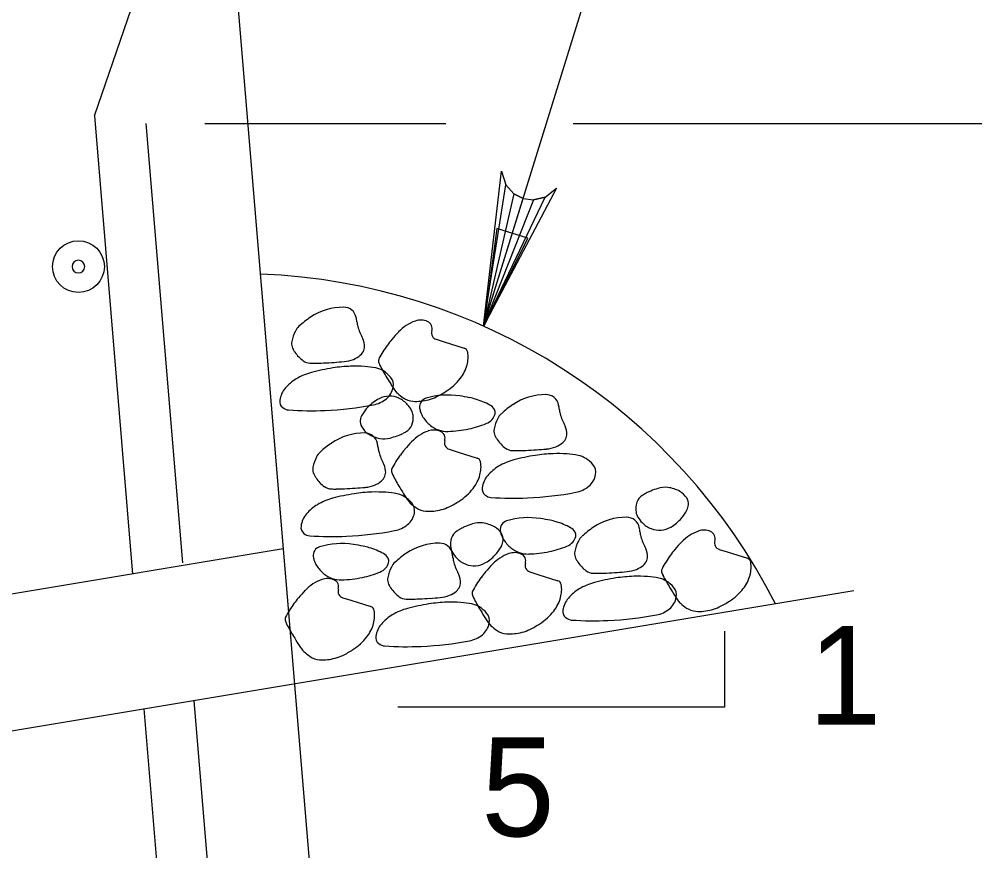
# Model space of a CAD drawing. Extents: x 634540 to 640306, y 296059 to 300275.
# Drawn here: x 639979.48 to 640008.5, y 298249.68 to 298274.94 of the extents above; entities that cross this region are included whole.
import ezdxf

# ---------------------------------------------------------------- set-up
doc = ezdxf.new("R2010")
doc.units = 0
for name, color, linetype in [('3', 7, 'Continuous'), ('4', 7, 'Continuous'), ('6', 7, 'Continuous'), ('8', 7, 'Continuous'), ('9', 7, 'Continuous')]:
    doc.layers.add(name, color=color, linetype=linetype)

# ---------------------------------------------------------------- blocks, each defined once
blk = doc.blocks.new('B')
at = {"layer": '3'}
blk.add_circle((0, 0), 0.1599, dxfattribs=at)
for start, end in [(0, 180), (180, 0)]:
    blk.add_arc((0, 0), 0.0391, start, end, dxfattribs=at)

msp = doc.modelspace()

# ---------------------------------------------------------------- linework, layer by layer
at = {"layer": '4'}
for p, q in [((639993.578, 298265.615), (639999.839, 298285.82)), ((639985.118, 298271.77), (639992.434, 298271.77)), ((639996.304, 298271.77), (640045.119, 298271.77))]:
    msp.add_line(p, q, dxfattribs=at)
for points in [[(639993.578, 298265.615), (639994.122, 298270.326), (639994.255, 298269.909), (639994.497, 298269.64), (639994.78, 298269.496), (639995.095, 298269.455), (639995.449, 298269.538), (639995.793, 298269.809), (639993.578, 298265.615), (639995.449, 298269.538), (639995.095, 298269.455), (639993.578, 298265.615), (639994.78, 298269.496), (639994.497, 298269.64), (639993.578, 298265.615), (639994.255, 298269.909)], [(640000.895, 298256.35), (640000.895, 298254.044), (639990.972, 298254.044)]]:
    msp.add_lwpolyline(points, dxfattribs=at)
msp.add_lwpolyline([(639994.922, 298268.29), (639993.98, 298268.578), (639993.591, 298265.609)], close=True, dxfattribs=at)
at = {"layer": '6'}
for p, q in [((639981.765, 298272.003), (639983.007, 298275.626)), ((639981.765, 298272.003), (639982.925, 298258.086)), ((639983.328, 298271.769), (639984.44, 298258.427)), ((639984.788, 298254.242), (639989.938, 298192.437)), ((639983.267, 298253.987), (639986.817, 298211.379))]:
    msp.add_line(p, q, dxfattribs=at)
at = {"layer": '8'}
for points in [[(639992.14, 298265.217), (639992.384, 298265.14), (639992.995, 298264.946)], [(639992.532, 298261.877), (639992.776, 298261.8), (639993.388, 298261.609)], [(640000.733, 298258.836), (640000.978, 298258.758), (640001.589, 298258.567)], [(639994.98, 298258.154), (639995.226, 298258.075), (639995.836, 298257.883)], [(639989.303, 298257.367), (639989.549, 298257.29), (639990.159, 298257.096)]]:
    msp.add_lwpolyline(points, dxfattribs=at)
for centre, radius, start, end in [((639989.318, 298264.416), 1.776, 89.5772, 124.1443), ((639989.328, 298265.798), 0.395, 11.4529, 89.5772), ((639989.973, 298263.45), 2.944, 124.1443, 132.7374), ((639988.393, 298265.608), 1.349, 6.1004, 11.4529), ((639991.676, 298265.297), 0.503, 65.9597, 109.6635), ((639988.319, 298265.24), 0.507, 132.7374, 153.538), ((639990.636, 298265.848), 0.907, 186.1004, 192.6291), ((639991.052, 298265.941), 1.333, 192.6291, 208.6753), ((639991.943, 298264.548), 1.298, 109.6635, 136.4562), ((639991.787, 298265.545), 0.231, 342.3569, 65.9597), ((639989.015, 298264.894), 1.284, 153.538, 168.4897), ((639989.272, 298264.968), 0.696, 6.391, 28.6753), ((639992.931, 298263.399), 2.801, 139.6491, 144.1424), ((639995.023, 298261.622), 5.547, 136.4562, 139.6491), ((639992.202, 298265.413), 0.205, 162.3569, 252.4715), ((639988.061, 298265.088), 0.311, 168.4897, 199.1639), ((639988.291, 298265.168), 0.554, 199.1639, 207.4728), ((639989.621, 298265.007), 0.344, 338.0834, 6.391), ((639993.462, 298263.015), 3.458, 144.1424, 152.1777), ((639992.951, 298264.806), 0.148, 9.0416, 72.4715), ((639988.584, 298265.32), 0.884, 207.4728, 214.0468), ((639988.726, 298265.416), 1.056, 214.0468, 234.0353), ((639989.362, 298265.283), 0.726, 291.5731, 310.9894), ((639989.592, 298265.018), 0.375, 310.9894, 338.0834), ((639990.525, 298264.565), 0.136, 152.1777, 193.5774), ((639992.171, 298264.682), 0.939, 344.9373, 9.0416), ((639988.321, 298264.859), 0.367, 234.0353, 268.2715), ((639988.412, 298267.862), 3.372, 268.2715, 270.9097), ((639990.026, 298257.942), 6.485, 99.0416, 104.9239), ((639988.327, 298273.236), 8.746, 270.9097, 272.5478), ((639988.079, 298278.805), 14.321, 272.5478, 273.846), ((639989.677, 298260.133), 4.267, 91.7881, 99.0416), ((639988.171, 298277.434), 12.947, 273.846, 275.2114), ((639989.254, 298265.556), 1.019, 275.2114, 291.5731), ((639989.675, 298260.197), 4.203, 86.0442, 91.7881), ((639989.771, 298261.584), 2.813, 79.021, 86.0442), ((639990.174, 298263.66), 0.698, 58.4341, 79.021), ((639990.862, 298264.646), 0.482, 193.5774, 207.4728), ((639996.193, 298267.418), 6.491, 207.4728, 211.2525), ((639991.97, 298264.736), 1.147, 321.7572, 344.9373), ((639988.821, 298262.461), 1.809, 104.9239, 120.8473), ((639990.057, 298263.47), 0.921, 40.5338, 58.4341), ((640005.472, 298273.05), 17.346, 211.2525, 212.2356), ((639990.478, 298263.831), 0.366, 349.0625, 40.5338), ((639988.593, 298262.843), 1.364, 120.8473, 139.2037), ((639990.245, 298263.876), 0.604, 309.5539, 349.0625), ((639993.996, 298265.813), 3.778, 212.2356, 214.3424), ((639991.491, 298265.113), 1.756, 303.0692, 321.7572), ((639988.099, 298263.269), 0.712, 139.2037, 172.3458), ((639990.727, 298262.8), 0.69, 91.376, 117.4803), ((639990.727, 298262.809), 0.681, 65.3457, 91.376), ((639991.351, 298264.006), 0.575, 214.3424, 227.6953), ((639992.158, 298264.892), 1.774, 227.6953, 235.2847), ((639992.504, 298261.197), 2.327, 81.3134, 106.8084), ((639991.555, 298264.685), 1.351, 285.2565, 295.7443), ((639990.941, 298265.958), 2.765, 295.7443, 303.0692), ((639991.925, 298257.406), 6.162, 78.4814, 81.3134), ((639995.462, 298261.761), 1.776, 89.5772, 124.1443), ((639995.472, 298263.142), 0.395, 11.4529, 89.5772), ((639987.639, 298263.331), 0.247, 172.3458, 230.2635), ((639988.352, 298273.126), 10.078, 272.3841, 280.7777), ((639991.006, 298262.264), 1.295, 117.4803, 136.4654), ((639990.073, 298264.084), 0.874, 280.7777, 309.5539), ((639990.685, 298262.718), 0.78, 41.057, 65.3457), ((639991.472, 298263.903), 0.569, 235.2847, 266.0442), ((639990.588, 298262.633), 0.91, 27.4728, 41.057), ((639991.532, 298264.769), 1.438, 266.0442, 285.2565), ((639991.911, 298263.161), 0.275, 106.8084, 186.6218), ((639992.7, 298261.208), 2.282, 73.8272, 78.4814), ((639992.741, 298261.349), 2.134, 61.1605, 73.8272), ((639993.598, 298262.907), 0.357, 29.8544, 61.1605), ((639996.117, 298260.795), 2.944, 124.1443, 132.7374), ((639994.537, 298262.953), 1.349, 6.1004, 11.4529), ((639987.681, 298263.382), 0.312, 230.2635, 266.2346), ((639988.34, 298273.403), 10.356, 266.2346, 272.3841), ((639990.249, 298262.713), 0.414, 149.2422, 171.9761), ((639991.01, 298262.26), 1.3, 136.4654, 149.2422), ((639990.999, 298262.847), 0.447, 8.0357, 27.4728), ((639990.871, 298262.829), 0.576, 337.0418, 8.0357), ((639992.219, 298263.197), 0.585, 186.6218, 200.3491), ((639992.337, 298263.241), 0.711, 200.3491, 212.797), ((639993.561, 298263.036), 0.376, 317.8475, 347.2445), ((639993.749, 298262.993), 0.183, 347.2445, 29.8544), ((639994.463, 298262.584), 0.507, 132.7374, 153.538), ((639996.78, 298263.193), 0.907, 186.1004, 192.6291), ((639997.196, 298263.286), 1.333, 192.6291, 208.6753), ((639990.175, 298262.723), 0.34, 171.9761, 209.5935), ((639991.029, 298262.762), 0.404, 299.831, 337.0418), ((639992.662, 298263.45), 1.097, 212.797, 230.2213), ((639992.476, 298263.227), 0.808, 230.2213, 250.5601), ((639992.49, 298265.548), 3.119, 281.8686, 292.039), ((639993.476, 298263.113), 0.491, 292.039, 317.8475), ((639995.159, 298262.238), 1.284, 153.538, 168.4897), ((639995.416, 298262.312), 0.696, 6.391, 28.6753), ((639989.961, 298260.595), 1.776, 89.5772, 124.1443), ((639990.401, 298262.852), 0.6, 209.5935, 237.6667), ((639989.971, 298261.977), 0.395, 11.4529, 89.5772), ((639990.628, 298263.21), 1.024, 237.6667, 259.0544), ((639990.559, 298263.482), 1.262, 288.5059, 293.8705), ((639990.61, 298263.366), 1.135, 293.8705, 297.4803), ((639989.899, 298264.733), 2.676, 297.4803, 299.831), ((639992.336, 298261.209), 1.298, 109.6635, 136.4562), ((639992.068, 298261.958), 0.503, 65.9597, 109.6635), ((639992.474, 298263.221), 0.802, 250.5601, 271.915), ((639992.179, 298262.207), 0.231, 342.3569, 65.9597), ((639992.379, 298266.075), 3.657, 271.915, 281.8686), ((639994.205, 298262.432), 0.311, 168.4897, 199.1639), ((639994.435, 298262.512), 0.554, 199.1639, 207.4728), ((639995.765, 298262.351), 0.344, 338.0834, 6.391), ((639990.616, 298259.629), 2.944, 124.1443, 132.7374), ((639989.036, 298261.787), 1.349, 6.1004, 11.4529), ((639990.559, 298262.854), 0.661, 259.0544, 285.7584), ((639989.433, 298266.846), 4.81, 285.7584, 288.5059), ((639995.415, 298258.283), 5.547, 136.4562, 139.6491), ((639992.595, 298262.074), 0.205, 162.3569, 252.4715), ((639994.728, 298262.665), 0.884, 207.4728, 214.0468), ((639994.87, 298262.761), 1.056, 214.0468, 234.0353), ((639995.507, 298262.627), 0.726, 291.5731, 310.9894), ((639995.737, 298262.363), 0.375, 310.9894, 338.0834), ((639988.962, 298261.419), 0.507, 132.7374, 153.538), ((639991.279, 298262.027), 0.907, 186.1004, 192.6291), ((639991.695, 298262.12), 1.333, 192.6291, 208.6753), ((639993.323, 298260.06), 2.801, 139.6491, 144.1424), ((639994.466, 298262.203), 0.367, 234.0353, 268.2715), ((639994.556, 298265.207), 3.372, 268.2715, 270.9097), ((639994.471, 298270.58), 8.746, 270.9097, 272.5478), ((639994.223, 298276.149), 14.321, 272.5478, 273.846), ((639995.821, 298257.477), 4.267, 91.7881, 99.0416), ((639994.315, 298274.778), 12.947, 273.846, 275.2114), ((639995.399, 298262.9), 1.019, 275.2114, 291.5731), ((639995.819, 298257.541), 4.203, 86.0442, 91.7881), ((639995.915, 298258.929), 2.813, 79.021, 86.0442), ((639989.658, 298261.073), 1.284, 153.538, 168.4897), ((639989.915, 298261.147), 0.696, 6.391, 28.6753), ((639993.855, 298259.676), 3.458, 144.1424, 152.1777), ((639993.344, 298261.467), 0.148, 9.0416, 72.4715), ((639992.563, 298261.343), 0.939, 344.9373, 9.0416), ((639994.965, 298259.806), 1.809, 104.9239, 120.8473), ((639996.17, 298255.287), 6.485, 99.0416, 104.9239), ((639996.318, 298261.005), 0.698, 58.4341, 79.021), ((639996.201, 298260.815), 0.921, 40.5338, 58.4341), ((639988.704, 298261.267), 0.311, 168.4897, 199.1639), ((639988.934, 298261.347), 0.554, 199.1639, 207.4728), ((639990.264, 298261.186), 0.344, 338.0834, 6.391), ((639990.917, 298261.226), 0.136, 152.1777, 193.5774), ((639991.254, 298261.308), 0.482, 193.5774, 207.4728), ((639994.737, 298260.187), 1.364, 120.8473, 139.2037), ((639996.623, 298261.175), 0.366, 349.0625, 40.5338), ((639989.227, 298261.499), 0.884, 207.4728, 214.0468), ((639989.369, 298261.595), 1.056, 214.0468, 234.0353), ((639990.006, 298261.462), 0.726, 291.5731, 310.9894), ((639990.235, 298261.197), 0.375, 310.9894, 338.0834), ((639996.585, 298264.08), 6.491, 207.4728, 211.2525), ((639992.362, 298261.397), 1.147, 321.7572, 344.9373), ((639994.244, 298260.614), 0.712, 139.2037, 172.3458), ((639996.389, 298261.22), 0.604, 309.5539, 349.0625), ((639988.965, 298261.038), 0.367, 234.0353, 268.2715), ((639989.055, 298264.041), 3.372, 268.2715, 270.9097), ((639988.97, 298269.415), 8.746, 270.9097, 272.5478), ((639988.722, 298274.984), 14.321, 272.5478, 273.846), ((639990.32, 298256.312), 4.267, 91.7881, 99.0416), ((639988.814, 298273.613), 12.947, 273.846, 275.2114), ((639989.898, 298261.735), 1.019, 275.2114, 291.5731), ((639990.318, 298256.376), 4.203, 86.0442, 91.7881), ((639990.414, 298257.763), 2.813, 79.021, 86.0442), ((640005.865, 298269.711), 17.346, 211.2525, 212.2356), ((639991.884, 298261.774), 1.756, 303.0692, 321.7572), ((639993.783, 298260.675), 0.247, 172.3458, 230.2635), ((639994.496, 298270.47), 10.078, 272.3841, 280.7777), ((639996.217, 298261.428), 0.874, 280.7777, 309.5539), ((639999.12, 298259.435), 1.262, 111.6288, 116.9933), ((640000.428, 298256.137), 4.81, 108.8812, 111.6288), ((639999.085, 298260.062), 0.661, 82.1773, 108.8812), ((639999.036, 298259.703), 1.024, 60.7895, 82.1773), ((639999.243, 298260.073), 0.6, 32.7163, 60.7895), ((639989.464, 298258.64), 1.809, 104.9239, 120.8473), ((639990.669, 298254.121), 6.485, 99.0416, 104.9239), ((639990.817, 298259.839), 0.698, 58.4341, 79.021), ((639990.7, 298259.649), 0.921, 40.5338, 58.4341), ((639994.388, 298262.474), 3.778, 212.2356, 214.3424), ((639991.743, 298260.667), 0.575, 214.3424, 227.6953), ((639991.333, 298262.62), 2.765, 295.7443, 303.0692), ((639993.825, 298260.726), 0.312, 230.2635, 266.2346), ((639994.484, 298270.747), 10.356, 266.2346, 272.3841), ((639998.611, 298260.129), 0.404, 122.9538, 160.1647), ((639999.847, 298258.222), 2.676, 120.6031, 122.9538), ((639999.063, 298259.548), 1.135, 116.9933, 120.6031), ((639999.462, 298260.214), 0.34, 355.0989, 32.7163), ((639989.236, 298259.022), 1.364, 120.8473, 139.2037), ((639992.55, 298261.554), 1.774, 227.6953, 235.2847), ((639991.122, 298260.01), 0.366, 349.0625, 40.5338), ((639991.864, 298260.564), 0.569, 235.2847, 266.0442), ((639991.924, 298261.431), 1.438, 266.0442, 285.2565), ((639991.948, 298261.346), 1.351, 285.2565, 295.7443), ((639998.773, 298260.07), 0.576, 160.1647, 191.1585), ((639998.603, 298260.631), 1.3, 319.5882, 332.365), ((639999.388, 298260.22), 0.414, 332.365, 355.0989), ((639988.743, 298259.448), 0.712, 139.2037, 172.3458), ((639990.888, 298260.055), 0.604, 309.5539, 349.0625), ((639994.36, 298259.436), 0.275, 106.8084, 186.6218), ((639994.953, 298257.472), 2.327, 81.3134, 106.8084), ((639994.374, 298253.681), 6.162, 78.4814, 81.3134), ((639995.149, 298257.482), 2.282, 73.8272, 78.4814), ((639997.911, 298258.036), 1.776, 89.5772, 124.1443), ((639997.921, 298259.417), 0.395, 11.4529, 89.5772), ((639998.646, 298260.045), 0.447, 191.1585, 210.5956), ((639999.045, 298260.281), 0.91, 210.5956, 224.1798), ((639998.607, 298260.627), 1.295, 300.6031, 319.5882), ((639988.282, 298259.51), 0.247, 172.3458, 230.2635), ((639988.995, 298269.305), 10.078, 272.3841, 280.7777), ((639990.716, 298260.263), 0.874, 280.7777, 309.5539), ((639994.222, 298257.142), 2.676, 120.6031, 122.9538), ((639993.437, 298258.468), 1.135, 116.9933, 120.6031), ((639993.495, 298258.355), 1.262, 111.6288, 116.9933), ((639994.802, 298255.057), 4.81, 108.8812, 111.6288), ((639993.46, 298258.982), 0.661, 82.1773, 108.8812), ((639993.411, 298258.623), 1.024, 60.7895, 82.1773), ((639993.618, 298258.993), 0.6, 32.7163, 60.7895), ((639994.668, 298259.472), 0.585, 186.6218, 200.3491), ((639995.19, 298257.624), 2.134, 61.1605, 73.8272), ((639996.047, 298259.182), 0.357, 29.8544, 61.1605), ((639998.566, 298257.07), 2.944, 124.1443, 132.7374), ((639996.986, 298259.228), 1.349, 6.1004, 11.4529), ((639998.952, 298260.191), 0.78, 224.1798, 248.4685), ((639998.916, 298260.098), 0.681, 248.4685, 274.4988), ((639998.915, 298260.107), 0.69, 274.4988, 300.6031), ((640000.269, 298258.917), 0.503, 65.9597, 109.6635), ((639988.324, 298259.56), 0.312, 230.2635, 266.2346), ((639988.983, 298269.582), 10.356, 266.2346, 272.3841), ((639993.147, 298258.99), 0.576, 160.1647, 191.1585), ((639992.986, 298259.048), 0.404, 122.9538, 160.1647), ((639994.786, 298259.516), 0.711, 200.3491, 212.797), ((639993.837, 298259.134), 0.34, 355.0989, 32.7163), ((639995.11, 298259.725), 1.097, 212.797, 230.2213), ((639996.01, 298259.31), 0.376, 317.8475, 347.2445), ((639996.198, 298259.268), 0.183, 347.2445, 29.8544), ((639996.912, 298258.859), 0.507, 132.7374, 153.538), ((639999.229, 298259.468), 0.907, 186.1004, 192.6291), ((639999.645, 298259.561), 1.333, 192.6291, 208.6753), ((640000.537, 298258.168), 1.298, 109.6635, 136.4562), ((640000.38, 298259.165), 0.231, 342.3569, 65.9597), ((639988.683, 298258.649), 0.275, 106.8084, 186.6218), ((639989.276, 298256.685), 2.327, 81.3134, 106.8084), ((639988.697, 298252.894), 6.162, 78.4814, 81.3134), ((639989.471, 298256.695), 2.282, 73.8272, 78.4814), ((639989.512, 298256.837), 2.134, 61.1605, 73.8272), ((639992.233, 298257.248), 1.776, 89.5772, 124.1443), ((639992.244, 298258.63), 0.395, 11.4529, 89.5772), ((639993.021, 298258.965), 0.447, 191.1585, 210.5956), ((639992.978, 298259.551), 1.3, 319.5882, 332.365), ((639993.762, 298259.14), 0.414, 332.365, 355.0989), ((639994.925, 298259.502), 0.808, 230.2213, 250.5601), ((639994.938, 298261.823), 3.119, 281.8686, 292.039), ((639995.924, 298259.388), 0.491, 292.039, 317.8475), ((639997.608, 298258.513), 1.284, 153.538, 168.4897), ((639997.865, 298258.587), 0.696, 6.391, 28.6753), ((640001.524, 298257.019), 2.801, 139.6491, 144.1424), ((640003.616, 298255.241), 5.547, 136.4562, 139.6491), ((640000.796, 298259.033), 0.205, 162.3569, 252.4715), ((639988.991, 298258.684), 0.585, 186.6218, 200.3491), ((639990.37, 298258.394), 0.357, 29.8544, 61.1605), ((639990.52, 298258.481), 0.183, 347.2445, 29.8544), ((639992.889, 298256.282), 2.944, 124.1443, 132.7374), ((639991.308, 298258.44), 1.349, 6.1004, 11.4529), ((639993.42, 298259.201), 0.91, 210.5956, 224.1798), ((639993.552, 298258.68), 0.907, 186.1004, 192.6291), ((639993.327, 298259.111), 0.78, 224.1798, 248.4685), ((639992.982, 298259.547), 1.295, 300.6031, 319.5882), ((639994.785, 298257.484), 1.298, 109.6635, 136.4562), ((639994.517, 298258.233), 0.503, 65.9597, 109.6635), ((639994.923, 298259.496), 0.802, 250.5601, 271.915), ((639994.628, 298258.482), 0.231, 342.3569, 65.9597), ((639994.828, 298262.35), 3.657, 271.915, 281.8686), ((639996.654, 298258.707), 0.311, 168.4897, 199.1639), ((639996.884, 298258.787), 0.554, 199.1639, 207.4728), ((639997.177, 298258.94), 0.884, 207.4728, 214.0468), ((639998.214, 298258.626), 0.344, 338.0834, 6.391), ((640002.056, 298256.634), 3.458, 144.1424, 152.1777), ((640001.545, 298258.426), 0.148, 9.0416, 72.4715), ((639989.109, 298258.728), 0.711, 200.3491, 212.797), ((639989.433, 298258.937), 1.097, 212.797, 230.2213), ((639990.247, 298258.601), 0.491, 292.039, 317.8475), ((639990.332, 298258.523), 0.376, 317.8475, 347.2445), ((639991.93, 298257.726), 1.284, 153.538, 168.4897), ((639991.235, 298258.072), 0.507, 132.7374, 153.538), ((639993.968, 298258.773), 1.333, 192.6291, 208.6753), ((639993.29, 298259.018), 0.681, 248.4685, 274.4988), ((639993.29, 298259.027), 0.69, 274.4988, 300.6031), ((639997.864, 298254.558), 5.547, 136.4562, 139.6491), ((639995.044, 298258.349), 0.205, 162.3569, 252.4715), ((639997.319, 298259.036), 1.056, 214.0468, 234.0353), ((639997.955, 298258.902), 0.726, 291.5731, 310.9894), ((639998.185, 298258.638), 0.375, 310.9894, 338.0834), ((639999.118, 298258.184), 0.136, 152.1777, 193.5774), ((640000.764, 298258.301), 0.939, 344.9373, 9.0416), ((639988.84, 298257.446), 0.503, 65.9597, 109.6635), ((639989.248, 298258.715), 0.808, 230.2213, 250.5601), ((639989.246, 298258.709), 0.802, 250.5601, 271.915), ((639989.15, 298261.563), 3.657, 271.915, 281.8686), ((639989.261, 298261.036), 3.119, 281.8686, 292.039), ((639990.977, 298257.92), 0.311, 168.4897, 199.1639), ((639992.188, 298257.8), 0.696, 6.391, 28.6753), ((639996.304, 298255.951), 3.458, 144.1424, 152.1777), ((639995.772, 298256.335), 2.801, 139.6491, 144.1424), ((639996.915, 298258.478), 0.367, 234.0353, 268.2715), ((639997.005, 298261.482), 3.372, 268.2715, 270.9097), ((639998.619, 298251.562), 6.485, 99.0416, 104.9239), ((639996.92, 298266.855), 8.746, 270.9097, 272.5478), ((639996.672, 298272.424), 14.321, 272.5478, 273.846), ((639998.27, 298253.752), 4.267, 91.7881, 99.0416), ((639996.764, 298271.053), 12.947, 273.846, 275.2114), ((639997.848, 298259.175), 1.019, 275.2114, 291.5731), ((639998.268, 298253.816), 4.203, 86.0442, 91.7881), ((639998.364, 298255.204), 2.813, 79.021, 86.0442), ((639998.767, 298257.28), 0.698, 58.4341, 79.021), ((639999.455, 298258.266), 0.482, 193.5774, 207.4728), ((640004.786, 298261.038), 6.491, 207.4728, 211.2525), ((640000.563, 298258.355), 1.147, 321.7572, 344.9373), ((639989.107, 298256.697), 1.298, 109.6635, 136.4562), ((639988.95, 298257.694), 0.231, 342.3569, 65.9597), ((639991.206, 298258), 0.554, 199.1639, 207.4728), ((639991.499, 298258.152), 0.884, 207.4728, 214.0468), ((639992.508, 298257.85), 0.375, 310.9894, 338.0834), ((639992.537, 298257.839), 0.344, 338.0834, 6.391), ((639995.793, 298257.742), 0.148, 9.0416, 72.4715), ((639995.012, 298257.618), 0.939, 344.9373, 9.0416), ((639997.414, 298256.08), 1.809, 104.9239, 120.8473), ((639998.65, 298257.09), 0.921, 40.5338, 58.4341), ((640014.065, 298266.669), 17.346, 211.2525, 212.2356), ((639999.072, 298257.45), 0.366, 349.0625, 40.5338), ((639992.186, 298253.771), 5.547, 136.4562, 139.6491), ((639989.366, 298257.562), 0.205, 162.3569, 252.4715), ((639991.642, 298258.248), 1.056, 214.0468, 234.0353), ((639991.237, 298257.691), 0.367, 234.0353, 268.2715), ((639991.087, 298270.266), 12.947, 273.846, 275.2114), ((639992.17, 298258.388), 1.019, 275.2114, 291.5731), ((639992.278, 298258.115), 0.726, 291.5731, 310.9894), ((639993.366, 298257.501), 0.136, 152.1777, 193.5774), ((639993.703, 298257.583), 0.482, 193.5774, 207.4728), ((639994.811, 298257.672), 1.147, 321.7572, 344.9373), ((639997.186, 298256.462), 1.364, 120.8473, 139.2037), ((639998.838, 298257.495), 0.604, 309.5539, 349.0625), ((640002.589, 298259.432), 3.778, 212.2356, 214.3424), ((640000.085, 298258.732), 1.756, 303.0692, 321.7572), ((639990.626, 298255.164), 3.458, 144.1424, 152.1777), ((639990.094, 298255.548), 2.801, 139.6491, 144.1424), ((639990.115, 298256.955), 0.148, 9.0416, 72.4715), ((639991.328, 298260.694), 3.372, 268.2715, 270.9097), ((639992.941, 298250.774), 6.485, 99.0416, 104.9239), ((639991.242, 298266.068), 8.746, 270.9097, 272.5478), ((639990.995, 298271.637), 14.321, 272.5478, 273.846), ((639992.593, 298252.965), 4.267, 91.7881, 99.0416), ((639992.591, 298253.029), 4.203, 86.0442, 91.7881), ((639992.687, 298254.416), 2.813, 79.021, 86.0442), ((639993.089, 298256.492), 0.698, 58.4341, 79.021), ((639999.034, 298260.355), 6.491, 207.4728, 211.2525), ((639992.973, 298256.302), 0.921, 40.5338, 58.4341), ((639996.693, 298256.889), 0.712, 139.2037, 172.3458), ((639999.944, 298257.625), 0.575, 214.3424, 227.6953), ((640000.751, 298258.512), 1.774, 227.6953, 235.2847), ((640000.148, 298258.304), 1.351, 285.2565, 295.7443), ((639999.534, 298259.578), 2.765, 295.7443, 303.0692), ((639989.334, 298256.831), 0.939, 344.9373, 9.0416), ((639991.509, 298255.675), 1.364, 120.8473, 139.2037), ((639991.737, 298255.293), 1.809, 104.9239, 120.8473), ((640008.313, 298265.986), 17.346, 211.2525, 212.2356), ((639993.394, 298256.663), 0.366, 349.0625, 40.5338), ((639994.333, 298258.049), 1.756, 303.0692, 321.7572), ((639996.232, 298256.95), 0.247, 172.3458, 230.2635), ((639996.945, 298266.745), 10.078, 272.3841, 280.7777), ((639998.666, 298257.703), 0.874, 280.7777, 309.5539), ((640000.065, 298257.522), 0.569, 235.2847, 266.0442), ((640000.125, 298258.389), 1.438, 266.0442, 285.2565), ((639987.689, 298256.714), 0.136, 152.1777, 193.5774), ((639988.025, 298256.795), 0.482, 193.5774, 207.4728), ((639993.356, 298259.567), 6.491, 207.4728, 211.2525), ((639989.134, 298256.885), 1.147, 321.7572, 344.9373), ((639991.015, 298256.101), 0.712, 139.2037, 172.3458), ((639993.16, 298256.708), 0.604, 309.5539, 349.0625), ((639996.837, 298258.749), 3.778, 212.2356, 214.3424), ((639994.192, 298256.942), 0.575, 214.3424, 227.6953), ((639994.999, 298257.829), 1.774, 227.6953, 235.2847), ((639993.782, 298258.895), 2.765, 295.7443, 303.0692), ((639996.274, 298257.001), 0.312, 230.2635, 266.2346), ((639996.933, 298267.022), 10.356, 266.2346, 272.3841), ((639992.989, 298256.916), 0.874, 280.7777, 309.5539), ((639994.313, 298256.839), 0.569, 235.2847, 266.0442), ((639994.373, 298257.706), 1.438, 266.0442, 285.2565), ((639994.396, 298257.621), 1.351, 285.2565, 295.7443), ((640002.636, 298265.199), 17.346, 211.2525, 212.2356), ((639991.159, 298257.962), 3.778, 212.2356, 214.3424), ((639988.655, 298257.262), 1.756, 303.0692, 321.7572), ((639990.554, 298256.163), 0.247, 172.3458, 230.2635), ((639990.596, 298256.213), 0.312, 230.2635, 266.2346), ((639991.267, 298265.958), 10.078, 272.3841, 280.7777), ((639988.515, 298256.155), 0.575, 214.3424, 227.6953), ((639989.322, 298257.041), 1.774, 227.6953, 235.2847), ((639988.105, 298258.107), 2.765, 295.7443, 303.0692), ((639991.256, 298266.235), 10.356, 266.2346, 272.3841), ((639988.636, 298256.051), 0.569, 235.2847, 266.0442), ((639988.696, 298256.918), 1.438, 266.0442, 285.2565), ((639988.719, 298256.833), 1.351, 285.2565, 295.7443)]:
    msp.add_arc(centre, radius, start, end, dxfattribs=at)
at = {"layer": '9'}
for p, q in [((639980.221, 298346.098), (639991.576, 298209.842)), ((639987.492, 298258.848), (639961.702, 298254.55)), ((640004.818, 298257.579), (639961.702, 298250.394))]:
    msp.add_line(p, q, dxfattribs=at)
msp.add_arc((639986.097, 298248.88), 18.332, 26.9324, 87.7453, dxfattribs=at)

# ---------------------------------------------------------------- block references
at = {"layer": '3', "xscale": 4.921475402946, "yscale": 4.921475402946, "rotation": 90}
msp.add_blockref('B', (639981.28, 298267.426), dxfattribs=at)

# ---------------------------------------------------------------- texts
at = {"layer": '4'}
for s, p in [('1', (640003.433, 298253.51)), ('5', (639993.509, 298250.121))]:
    msp.add_text(s, height=3, dxfattribs=at).set_placement(p)

doc.saveas('drawing.dxf')
